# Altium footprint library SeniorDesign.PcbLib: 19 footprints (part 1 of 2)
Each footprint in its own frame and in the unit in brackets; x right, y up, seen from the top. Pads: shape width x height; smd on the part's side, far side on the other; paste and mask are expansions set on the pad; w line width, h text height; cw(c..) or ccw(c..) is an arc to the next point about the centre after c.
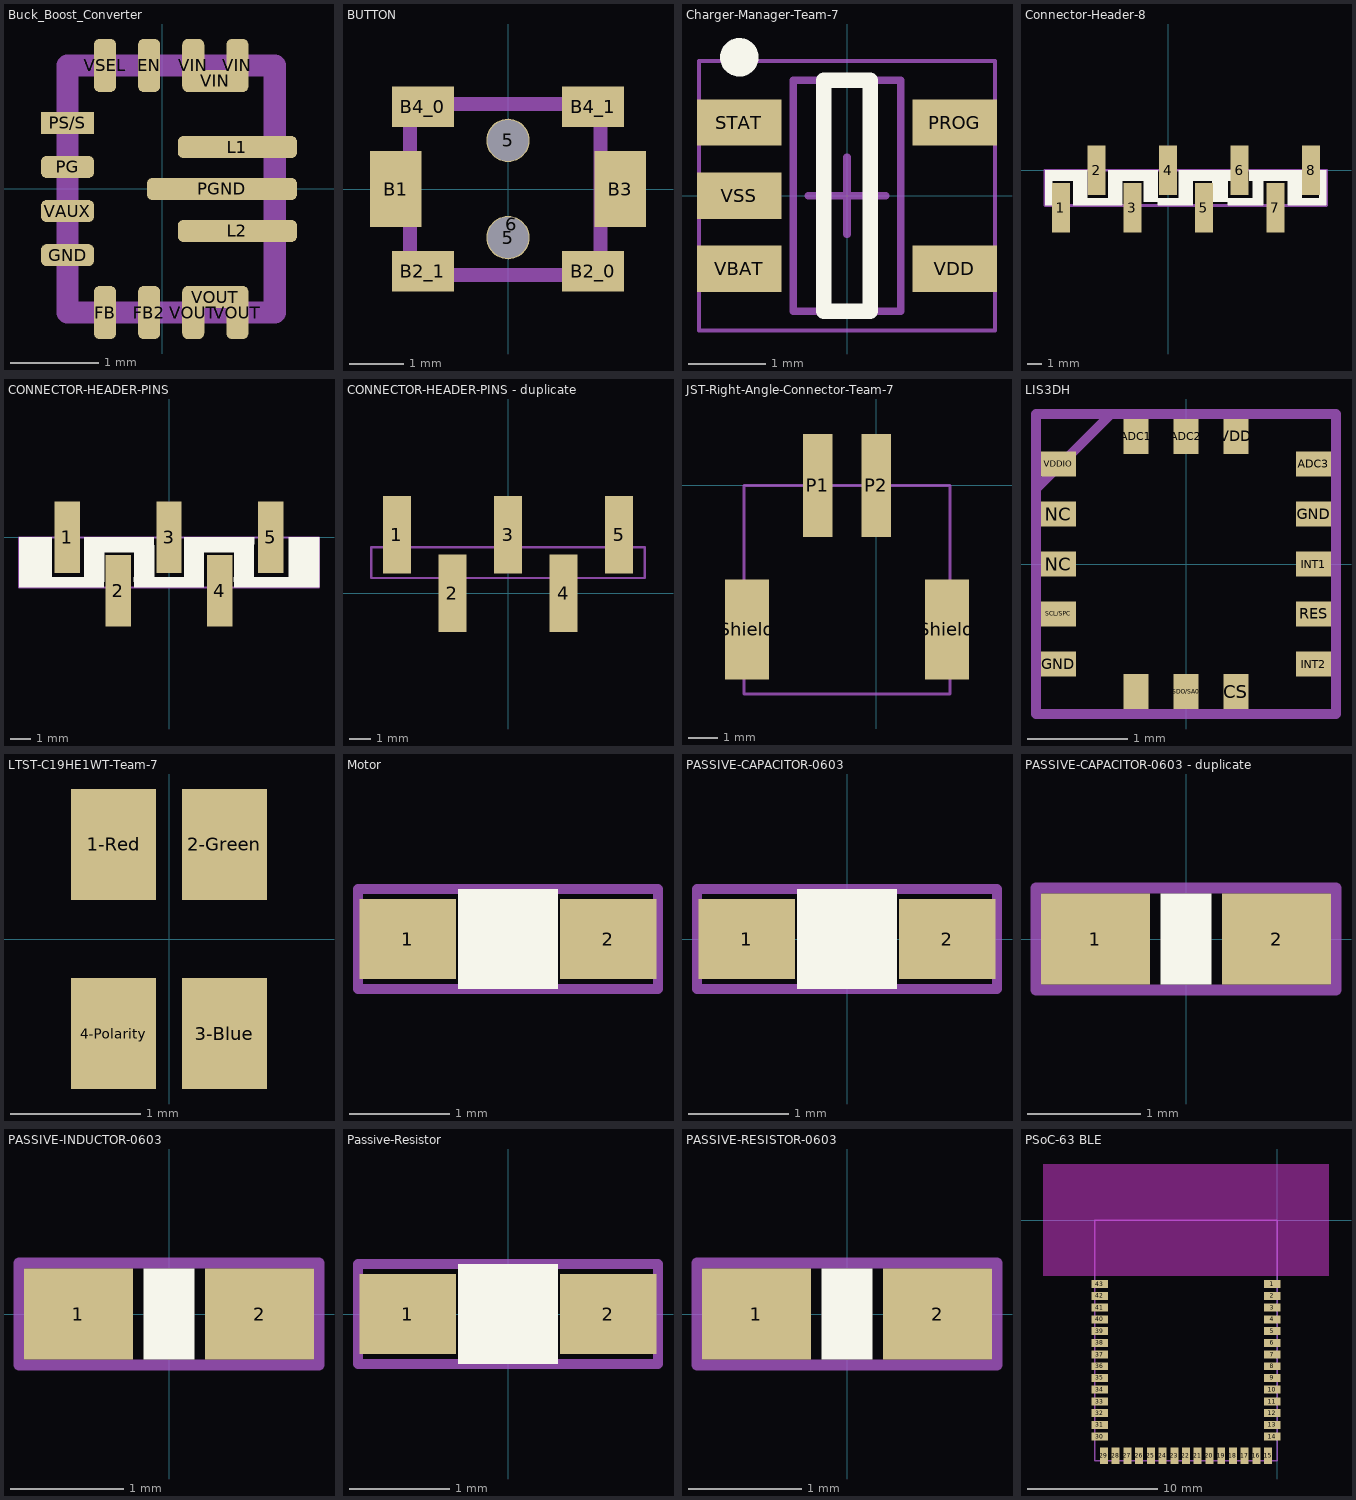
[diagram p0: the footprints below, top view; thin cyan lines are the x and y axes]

## Buck_Boost_Converter [mm] "Buck Boost Converter"
pads (17):
  rrect50% 0.25x0.6 smd: EN(-0.15,1.4) FB(-0.65,-1.4) FB2(-0.15,-1.4) VIN(0.35,1.4) VIN(0.85,1.4) VOUT(0.35,-1.4) VOUT(0.85,-1.4) VSEL(-0.65,1.4)
  rrect50% 0.6x0.25 smd: GND(-1.075,-0.75) PG(-1.075,0.25) VAUX(-1.075,-0.25)
  rrect50% 1.35x0.25 smd: L1(0.85,0.475) L2(0.85,-0.475)
  rrect50% 1.7x0.25 smd: PGND(0.675,0)
  rect 0.6x0.25 smd: PS/S(-1.075,0.75)
  rrect50% 0.75x0.25 smd: VIN(0.6,1.225) VOUT(0.6,-1.225)
Top Assembly:
  lines w0.254: -1.075,-1.4 -1.075,1.4 1.275,1.4 1.275,-1.4 -1.075,-1.4
  text ".Designator" at -2,-0.275 h0.4
3D body: height 0.4, standoff 0, extent -1.075,-1.425 1.275,1.4

## BUTTON [mm]
pads (9):
  round 0.8 hole 0.762 mask+0: 5(0,-0.9) 5(0,0.9)
  round 0.8 on Top Paste: 6(0.07,-0.653)
  rect 0.95x1.4 smd: B1(-2.075,0) B3(2.075,0)
  rect 1.15x0.75 smd: B2_0(1.575,-1.525) B2_1(-1.575,-1.525) B4_0(-1.575,1.525) B4_1(1.575,1.525)
Top Assembly:
  lines w0.254: -1.815,-1.591 1.71,-1.591 1.71,1.571 1.709,1.572 -1.815,1.572 -1.815,-1.591
  text ".Designator" at -3.139,-0.475 h0.75

## Charger-Manager-Team-7 [mm]
height 1.1
pads (5):
  rect 1.1x0.6 smd: PROG(1.4,0.95) STAT(-1.4,0.95) VBAT(-1.4,-0.95) VDD(1.4,-0.95) VSS(-1.4,0)
Top Overlay:
  circle w0.25: c-1.4,1.8 r0.125
  lines w0.2: -0.3,-1.5 -0.3,1.5 0.3,1.5 0.3,-1.5 -0.3,-1.5
3D Bodies:
  lines w0.1: -0.7,-1.5 0.7,-1.5 0.7,1.5 -0.7,1.5 -0.7,-1.5
Mechanical 15:
  lines w0.05: -1.925,-1.75 1.925,-1.75 1.925,1.75 -1.925,1.75 -1.925,-1.75
  lines w0.1: -0.5,0 0.5,0 ; 0,-0.5 0,0.5
Top Assembly:
  text ".Designator" at -2,-0.067 h0.4
3D body: height 1.1, standoff 0.05, extent -0.7,-1.5 0.7,1.5

## Connector-Header-8 [mm]
pads (8):
  rect 1.27x3.54 smd: 1(-7.62,-2.67) 2(-5.08,0) 3(-2.54,-2.67) 4(0,0) 5(2.54,-2.67) 6(5.08,0) 7(7.62,-2.67) 8(10.16,0)
Top Overlay:
  region: 0.75,-2 1.75,-2 1.75,0
  region: 0.75,-2 0.75,0 2,0
  region: -1.75,-2.25 -1.75,-0.75 -0.75,-0.75 -0.75,-2.25
  region: -3.25,-0.75 -0.75,-0.75 -0.75,0 -3.25,0
  region: -5.75,-2 -3.25,-2 -3.25,-2.5 -5.75,-2.5
  region: -5.75,-0.75 -5.75,-2.5 -6.75,-2.5 -6.75,-0.75
  region: -0.75,-2 1.75,-2 1.75,-2.5 -0.75,-2.5
  region: -4.25,-2 -4.25,0 -3.25,0 -3.25,-2
  region: -8.75,-0.75 -5.75,-0.75 -5.75,0 -8.75,0
  region: 4.25,-2.25 4.25,-0.75 3.125,-0.75 3.125,-2.125 3,-2.25
  region: 5.75,-0.75 9.5,-0.75 9.5,0 5.75,0
  region: 1.75,-0.75 4.5,-0.75 4.5,0 1.75,0
  region: 9.5,-2 10.75,-2 10.75,-2.5 9.5,-2.5
  region: 4.25,-2 6.75,-2 6.75,-2.5 4.25,-2.5
  region: 6,-2 6,-0.75 6.75,-0.75 6.75,-2
  region: 8.5,-2.5 8.5,-0.75 9.5,-0.75 9.5,-2.5
  region: 10.75,0 11.25,0 11.25,-2.5 10.75,-2.5
  region: -8.25,-2.5 -8.25,-0.75 -8.75,-0.75 -8.75,-2.5
Top Assembly:
  lines w0.2: -8.75,-2.5 -8.75,0 8.75,0 11.25,0 11.25,-2.5 8.75,-2.5 -8.75,-2.5
  text ".Designator" at -0.15,-1.017 h0.4

## CONNECTOR-HEADER-PINS [mm]
pads (5):
  rect 1.27x3.56 smd: 1(-5.08,0) 2(-2.54,-2.67) 3(0,0) 4(2.54,-2.67) 5(5.08,0)
Top Overlay:
  region: -7.5,0 -5.875,0 -5.875,-2.5 -7.5,-2.5
  region: -6,-2 -3.25,-2 -3.25,-2.5 -6,-2.5
  region: -3.25,-2 -3.25,0 -4.25,0 -4.25,-2
  region: 6,0 7.5,0 7.5,-2.5 6,-2.5
  region: 3.25,-2 6,-2 6,-2.5 3.25,-2.5
  region: -1.75,-2 1.75,-2 1.75,-2.5 -1.75,-2.5
  region: 0.75,-2 0.75,0 1.75,0 1.75,-2
  region: 1.75,0 4.25,0 4.25,-0.75 1.75,-0.75
  region: 3.25,-0.75 4.25,-0.75 4.25,-2 3.25,-2
  region: -0.75,-2 -0.75,-0.75 -1.75,-0.75 -1.75,-2
  region: -3.25,0 -0.75,0 -0.75,-0.75 -3.25,-0.75
Top Assembly:
  lines w0.1: -7.5,-1 -6.5,0 ; -7.5,-2.5 -7.5,0 7.5,0 7.5,-2.5 -7.5,-2.5

## CONNECTOR-HEADER-PINS - duplicate [mm]
pads (5):
  rect 1.27x3.56 smd: 1(-5.08,2.67) 2(-2.54,0) 3(0,2.67) 4(2.54,0) 5(5.08,2.67)
Top Assembly:
  lines w0.1: -6.25,0.7 6.25,0.7 6.25,2.1 -6.25,2.1 -6.25,0.7
  text ".Designator" at -2.125,-0.375 h0.4
3D body: height 1, standoff 0, extent -6.25,0.675 6.25,2.075

## JST-Right-Angle-Connector-Team-7 [mm]
pads (4):
  rect 1x3.5 smd: P1(-2,0) P2(0,0)
  rect 1.5x3.4 smd: Shield(-4.4,-4.9) Shield(2.4,-4.9)
Top Assembly:
  lines w0.1: -4.5,-7.1 -4.5,0 2.5,0 2.5,-7.1 -4.5,-7.1
3D body "SM02B-PASS-TBT-LF--SN---3DModel-STEP-56544.STEP": height 5.7, standoff 0, extent -5.2,-8.1 2.8,1.9

## LIS3DH [mm]
pads (16):
  rect 0.25x0.35 smd: ADC1(-0.5,1.275) ADC2(0,1.275) CS(0.5,-1.275) SDA/SDI/SDO(-0.5,-1.275) SDO/SA0(0,-1.275) VDD(0.5,1.275)
  rect 0.35x0.25 smd: ADC3(1.275,1) GND(-1.275,-1) GND(1.275,0.5) INT1(1.275,0) INT2(1.275,-1) NC(-1.275,0) NC(-1.275,0.5) RES(1.275,-0.5) SCL/SPC(-1.275,-0.5) VDDIO(-1.275,1)
Top Assembly:
  lines w0.1: -1.5,0.75 -0.75,1.5 ; -1.5,-1.5 1.5,-1.5 1.5,1.5 -1.5,1.5 -1.5,-1.5
  text ".Designator" at -0.9,-0.017 h0.4
3D body: height 0.25, standoff 0, extent -1.5,-1.5 1.5,1.5

## LTST-C19HE1WT-Team-7 [mm]
pads (4):
  rect 0.65x0.85 smd: 1-Red(-0.425,0.725) 2-Green(0.425,0.725) 3-Blue(0.425,-0.725) 4-Polarity(-0.425,-0.725)
3D body "LTST-C19HE1WT--3DModel-STEP-56544.STEP": height 0.35, standoff 0, extent -0.8,-0.8 0.8,0.8

## Motor [mm]
pads (2):
  rect 0.965x0.8 smd: 1(-1263,252.8) 2(-1261,252.8)
Top Overlay:
  region: -1262.5,253.3 -1262.5,252.3 -1261.5,252.3 -1261.5,253.3
Top Assembly:
  lines w0.1: -1263.5,252.3 -1263.5,253.3 -1260.5,253.3 -1260.5,252.3 -1263.5,252.3
  text ".Designator" at -1262.9,253.033 h0.4

## PASSIVE-CAPACITOR-0603 [mm]
pads (2):
  rect 0.965x0.8 smd: 1(-1,0) 2(1,0)
Top Overlay:
  region: -0.5,0.5 0.5,0.5 0.5,-0.5 -0.5,-0.5
Top Assembly:
  lines w0.1: -1.5,-0.5 1.5,-0.5 1.5,0.5 -1.5,0.5 -1.5,-0.5
  text ".Designator" at -0.9,-0.3 h0.3

## PASSIVE-CAPACITOR-0603 - duplicate [mm]
pads (2):
  rect 0.965x0.8 smd: 1(-0.8,0) 2(0.8,0)
Top Overlay:
  region: -0.225,0.4 0.225,0.4 0.225,-0.4 -0.225,-0.4
Top Assembly:
  lines w0.1: -1.325,-0.45 -1.325,0.45 1.325,0.45 1.325,-0.45 -1.325,-0.45
  text ".Designator" at -1,-0.25 h0.4
3D body: height 0.4, standoff 0, extent -0.825,-0.4 0.8,0.4

## PASSIVE-INDUCTOR-0603 [mm] "Inductor"
pads (2):
  rect 0.965x0.8 smd: 1(-0.8,0) 2(0.8,0)
Top Overlay:
  region: -0.225,0.4 0.225,0.4 0.225,-0.4 -0.225,-0.4
Top Assembly:
  lines w0.1: -1.325,-0.45 -1.325,0.45 1.325,0.45 1.325,-0.45 -1.325,-0.45
  text ".Designator" at -1.975,-0.975 h0.4
3D body: height 0.4, standoff 0, extent -0.825,-0.4 0.8,0.4

## Passive-Resistor [mm]
pads (2):
  rect 0.965x0.8 smd: 1(-1,0) 2(1,0)
Top Overlay:
  region: -0.5,0.5 -0.5,-0.5 0.5,-0.5 0.5,0.5
Top Assembly:
  lines w0.1: -1.5,-0.5 1.5,-0.5 1.5,0.5 -1.5,0.5 -1.5,-0.5
  text ".Designator" at -0.9,0.233 h0.4

## PASSIVE-RESISTOR-0603 [mm]
pads (2):
  rect 0.965x0.8 smd: 1(-0.8,0) 2(0.8,0)
Top Overlay:
  region: -0.225,0.4 0.225,0.4 0.225,-0.4 -0.225,-0.4
Top Assembly:
  lines w0.1: -1.325,-0.45 -1.325,0.45 1.325,0.45 1.325,-0.45 -1.325,-0.45
  text ".Designator" at -1,-0.25 h0.4
3D body: height 0.4, standoff 0, extent -0.825,-0.4 0.8,0.4

## PSoC-63 BLE [mm]
pads (43):
  rect 1.27x0.61 smd: 1(-0.38,-4.93) 2(-0.38,-5.83) 3(-0.38,-6.73) 4(-0.38,-7.63) 5(-0.38,-8.54) 6(-0.38,-9.44) 7(-0.38,-10.34) 8(-0.38,-11.24) 9(-0.38,-12.14) 10(-0.38,-13.04) 11(-0.38,-13.95) 12(-0.38,-14.85) 13(-0.38,-15.75) 14(-0.38,-16.65) 30(-13.62,-16.65) 31(-13.62,-15.75) 32(-13.62,-14.85) 33(-13.62,-13.95) 34(-13.62,-13.04) 35(-13.62,-12.14) 36(-13.62,-11.24) 37(-13.62,-10.34) 38(-13.62,-9.44) 39(-13.62,-8.54) 40(-13.62,-7.63) 41(-13.62,-6.73) 42(-13.62,-5.83) 43(-13.62,-4.93)
  rect 0.61x1.27 smd: 15(-0.69,-18.12) 16(-1.59,-18.12) 17(-2.49,-18.12) 18(-3.39,-18.12) 19(-4.29,-18.12) 20(-5.2,-18.12) 21(-6.1,-18.12) 22(-7,-18.12) 23(-7.9,-18.12) 24(-8.8,-18.12) 25(-9.7,-18.12) 26(-10.61,-18.12) 27(-11.51,-18.12) 28(-12.41,-18.12) 29(-13.31,-18.12)
Top Layer keep-out:
  rectangle: -18,-4.31 4,4.31
Board Outline:
  lines w0.1: -14,-18.5 0,-18.5 0,0 -14,0 -14,-18.5
Top Assembly:
  text ".Designator" at -9.4,-10.1 h0.5
3D body: height 0.8, standoff 0, extent -14,-18.5 0,0
3D body: height 1.2, standoff 0, extent -14,-18.5 0,-4.299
